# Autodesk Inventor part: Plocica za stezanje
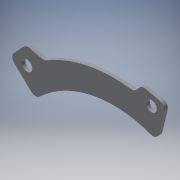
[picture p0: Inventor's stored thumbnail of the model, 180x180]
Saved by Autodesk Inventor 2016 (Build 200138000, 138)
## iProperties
Created: 2015-08
Part Number: Plocica za stezanje
Material: Generic
Document SubType Name: Modeling
Designer: Ugljesa
Density: 1 g/cm^3
Appearance: Default
Author: Ugljesa
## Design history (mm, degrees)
sketch "Sketch1"
  geometry: L1 (90.331, 34.953)-(93.579, 38.382); L2 (98.371, 39.807)-(110.153, 36.99); L3 (113.853, 30.964)-(109.392, 12.311); L4 (2.623, -10.358)-(-11.992, 3.486); L5 (-12.184, 10.555)-(-3.854, 19.349); L6 (0.939, 20.774)-(11.38, 18.277); L7 (71.497, -75.599)-(-37.732, 27.868); C1 r 4.5 at (-1.155, 6.995) reference; C2 r 4.5 at (103.271, 29.712); C3 r 4.5 at (103.271, 29.712) reference; A1 r 90 centre (71.497, -75.599) between (102.791, 8.786) and (9.506, -10.353); A2 r 110 centre (71.497, -75.599) between (86.04, 33.436) and (15.106, 18.847); A3 r 5 centre (-0.224, 15.911) between (0.939, 20.774) and (-3.854, 19.349); A4 r 5 centre (12.543, 23.14) between (11.38, 18.277) and (15.106, 18.847); A5 r 5 centre (86.701, 38.392) between (86.04, 33.436) and (90.331, 34.953); A6 r 5 centre (97.209, 34.944) between (98.371, 39.807) and (93.579, 38.382); A7 r 5 centre (108.99, 32.127) between (113.853, 30.964) and (110.153, 36.99); A8 r 5 centre (104.529, 13.474) between (102.791, 8.786) and (109.392, 12.311); A9 r 5 centre (6.062, -6.728) between (2.623, -10.358) and (9.506, -10.353); A10 r 5 centre (-8.554, 7.116) between (-12.184, 10.555) and (-11.992, 3.486); 9 further points
  constraints: 26 point on circle, 16 tangent, 14 end point, 12 centre point, 12 point on line, 7 equal radius, 2 coincident, 2 perpendicular, 1 collinear, 2 other
  dimensions: "d1" = 110 radius of A2; "d2" = 90 radius of A1; "d4" = 60 deg angle of L4 L3; "d5" = 30 distance of point (115.015, 35.827) point (108.038, 6.649); "d8" = 30 distance of point (6.158, -13.706) point (-15.622, 6.925); "d9" = 10 distance from line of L4 C1.centre; "d10" = 10 distance from line of L3 C2.centre; "d11" = 20 distance of point (95.564, 40.478) point (115.015, 35.827); "d12" = 20 distance of point (-15.622, 6.925) point (-1.868, 21.445); "d13" = 30 deg angle of L3 L1; "d14" = 30 deg angle of L7 L6; "d15" = 5 radius of A3
extrude "Extrusion1" new body sketch "Sketch1" distance "d16" = 3; taper "d17" = 0 deg
body "Solid1"
node "Reference1"
